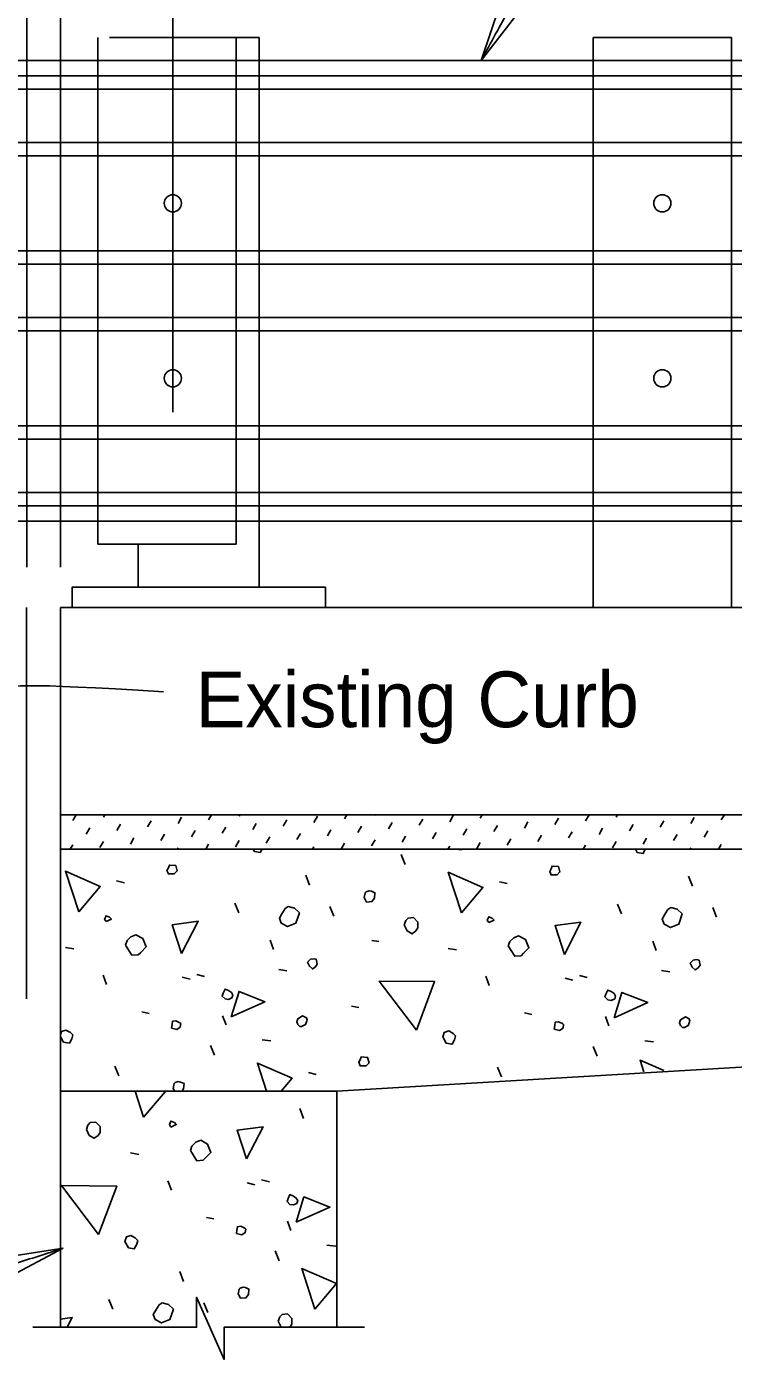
# Model space of a CAD drawing. Extents: x 0 to 41.1, y 0 to 25.9.
# Drawn here: x 27.563 to 30.119, y 5.148 to 9.971 of the extents above; entities that cross this region are included whole.
import ezdxf

# ---------------------------------------------------------------- set-up
doc = ezdxf.new("R2010")
doc.units = 0
for name, color, linetype in [('Dimension', 7, 'Continuous'), ('ExistSuperStruct', 7, 'Continuous'), ('Miscellaneous', 7, 'Continuous'), ('SteelMisc_h', 7, 'Continuous'), ('TextStructures', 7, 'Continuous')]:
    doc.layers.add(name, color=color, linetype=linetype)

msp = doc.modelspace()

# ---------------------------------------------------------------- linework, layer by layer
at = {"layer": 'Dimension'}
for p, q in [((27.5628, 8.0144), (27.5628, 11.1866)), ((27.6853, 8.0144), (27.6853, 11.1866))]:
    msp.add_line(p, q, dxfattribs=at)
for points in [[(29.2068, 9.8481), (29.3364, 10.0149), (29.2743, 10.0483)], [(27.6953, 5.5504), (27.4865, 5.5185), (27.5086, 5.4515)]]:
    msp.add_lwpolyline(points, close=True, dxfattribs=at)
msp.add_lwpolyline([(28.7853, 5.2645), (28.2767, 5.2645), (28.2767, 5.1482), (28.1774, 5.3732), (28.1774, 5.2645), (27.5853, 5.2645)], dxfattribs=at)
for points, degree in [([(30.0832, 10.4986), (29.8429, 10.4986), (29.6309, 10.4986), (29.4118, 10.2299), (29.2069, 9.8481)], 2), ([(28.0581, 7.5636), (27.5366, 7.5973), (27.4332, 7.5751), (27.3392, 7.5386), (27.1681, 7.276)], 3), ([(27.6953, 5.5504), (27.0315, 5.3308), (26.4276, 5.2844)], 2)]:
    msp.add_open_spline(points, degree=degree, dxfattribs=at)
at = {"layer": 'ExistSuperStruct'}
for p, q in [((27.5627, 7.8689), (27.5627, 6.4523)), ((27.6853, 7.869), (27.6853, 5.2644)), ((27.6853, 7.869), (28.6853, 7.869)), ((27.6853, 7.8689), (35.7954, 7.8689)), ((39.26, 7.1191), (27.6853, 7.1191)), ((27.6853, 6.994), (39.26, 6.994)), ((32.9053, 6.369), (28.6853, 6.119)), ((28.6853, 6.119), (27.6853, 6.119)), ((28.6853, 6.119), (28.6853, 5.2644))]:
    msp.add_line(p, q, dxfattribs=at)
at = {"layer": 'Miscellaneous'}
for p, q in [((28.0916, 8.5752), (28.0916, 11.3864)), ((27.8208, 9.9315), (27.8208, 8.0981)), ((27.8626, 9.9315), (28.4041, 9.9315)), ((28.3208, 9.9315), (28.3208, 8.0981)), ((29.6124, 9.9315), (29.6124, 7.869)), ((29.6124, 9.9315), (30.1124, 9.9315)), ((30.1124, 9.9315), (30.1124, 7.869)), ((26.2319, 9.7925), (37.5468, 9.7925)), ((26.2319, 9.7443), (37.5468, 9.7443)), ((26.2319, 9.5515), (37.5468, 9.5515)), ((26.2319, 9.5032), (37.5468, 9.5032)), ((26.2319, 9.1593), (37.5468, 9.1593)), ((26.2319, 9.1111), (37.5468, 9.1111)), ((26.2319, 8.9182), (37.5468, 8.9182)), ((26.2319, 8.8701), (37.5468, 8.8701)), ((26.2319, 8.5262), (37.5468, 8.5262)), ((26.2319, 8.4779), (37.5468, 8.4779)), ((26.2319, 8.2851), (37.5468, 8.2851)), ((26.2319, 8.2369), (37.5468, 8.2369)), ((27.7297, 7.0977), (27.7421, 7.1191)), ((27.8403, 7.1107), (27.8452, 7.1191)), ((27.9998, 7.0748), (28.0128, 7.0972)), ((28.1104, 7.0878), (28.1234, 7.1102)), ((28.2211, 7.1007), (28.2317, 7.1191)), ((28.3317, 7.1137), (28.3348, 7.1191)), ((28.4912, 7.0778), (28.5041, 7.1002)), ((28.6018, 7.0908), (28.6148, 7.1132)), ((28.7124, 7.1038), (28.7213, 7.1191)), ((28.8231, 7.1167), (28.8244, 7.1191)), ((28.8719, 7.0679), (28.8849, 7.0903)), ((28.9825, 7.0809), (28.9955, 7.1032)), ((29.0932, 7.0938), (29.1061, 7.1162)), ((29.2038, 7.1068), (29.2109, 7.1191)), ((29.3633, 7.0709), (29.3762, 7.0933)), ((29.4739, 7.0839), (29.4869, 7.1063)), ((29.5845, 7.0968), (29.5974, 7.1191)), ((29.6952, 7.1098), (29.7005, 7.1191)), ((29.8546, 7.0739), (29.8676, 7.0963)), ((29.9653, 7.0869), (29.9782, 7.1093)), ((30.0759, 7.0999), (30.087, 7.1191)), ((27.7785, 7.0489), (27.7915, 7.0713)), ((27.8892, 7.0619), (27.9021, 7.0842)), ((28.0486, 7.026), (28.0616, 7.0484)), ((28.1593, 7.0389), (28.1722, 7.0613)), ((28.2699, 7.0519), (28.2829, 7.0743)), ((28.3805, 7.0649), (28.3935, 7.0873)), ((28.54, 7.029), (28.553, 7.0514)), ((28.6506, 7.042), (28.6636, 7.0644)), ((28.7613, 7.0549), (28.7742, 7.0773)), ((28.9207, 7.0191), (28.9337, 7.0415)), ((29.0314, 7.032), (29.0443, 7.0544)), ((29.142, 7.045), (29.155, 7.0674)), ((29.2526, 7.058), (29.2656, 7.0803)), ((29.4121, 7.0221), (29.4251, 7.0445)), ((29.5227, 7.035), (29.5357, 7.0574)), ((29.6334, 7.048), (29.6463, 7.0704)), ((29.744, 7.061), (29.757, 7.0834)), ((29.9035, 7.0251), (29.9164, 7.0475)), ((30.0141, 7.0381), (30.0271, 7.0605)), ((27.7207, 6.994), (27.7297, 7.0095)), ((27.8274, 7.0001), (27.8403, 7.0224)), ((27.938, 7.013), (27.951, 7.0354)), ((28.1072, 6.994), (28.1104, 6.9995)), ((28.2104, 6.994), (28.2211, 7.0125)), ((28.3187, 7.0031), (28.3317, 7.0255)), ((28.4294, 7.016), (28.4423, 7.0384)), ((28.5969, 6.994), (28.6018, 7.0026)), ((28.7, 6.994), (28.7124, 7.0155)), ((28.8101, 7.0061), (28.8231, 7.0285)), ((29.0865, 6.994), (29.0932, 7.0056)), ((29.1149, 6.994), (29.1368, 6.9916)), ((29.1908, 6.9962), (29.2038, 7.0185)), ((29.3015, 7.0091), (29.3144, 7.0315)), ((29.473, 6.994), (29.4739, 6.9956)), ((29.5761, 6.994), (29.5845, 7.0086)), ((29.6822, 6.9992), (29.6952, 7.0216)), ((29.7928, 7.0121), (29.8058, 7.0345)), ((29.9626, 6.994), (29.9653, 6.9987)), ((30.0657, 6.994), (30.0759, 7.0116)), ((28.9323, 6.9392), (28.9182, 6.9745)), ((28.5865, 6.8643), (28.5723, 6.8997)), ((29.9711, 6.8608), (29.957, 6.8961)), ((27.8882, 6.8802), (27.9165, 6.8731)), ((29.2729, 6.8767), (29.3012, 6.8696)), ((28.3301, 6.7635), (28.316, 6.7989)), ((28.6742, 6.7518), (28.6601, 6.7871)), ((29.7148, 6.76), (29.7007, 6.7954)), ((30.0589, 6.7483), (30.0448, 6.7836)), ((28.4557, 6.631), (28.4433, 6.6645)), ((28.8121, 6.6634), (28.8369, 6.6599)), ((29.8403, 6.6274), (29.828, 6.661)), ((27.7032, 6.6387), (27.7333, 6.6333)), ((29.0879, 6.6351), (29.1179, 6.6298)), ((28.4745, 6.5591), (28.5045, 6.5538)), ((27.8517, 6.5043), (27.8393, 6.5379)), ((28.1257, 6.5308), (28.154, 6.5237)), ((28.1781, 6.5408), (28.2064, 6.5337)), ((29.2364, 6.5008), (29.224, 6.5344)), ((29.5104, 6.5273), (29.5387, 6.5202)), ((29.5628, 6.5373), (29.5911, 6.5302)), ((29.8592, 6.5556), (29.8892, 6.5503)), ((28.7379, 6.4265), (28.7644, 6.4212)), ((27.979, 6.4053), (28.0055, 6.4)), ((28.2842, 6.3582), (28.2718, 6.3918)), ((29.3637, 6.4018), (29.3902, 6.3965)), ((29.6689, 6.3547), (29.6565, 6.3883)), ((28.2418, 6.2486), (28.2276, 6.284)), ((28.4144, 6.3045), (28.4462, 6.301)), ((29.6264, 6.2451), (29.6123, 6.2804)), ((29.799, 6.301), (29.8309, 6.2975)), ((27.8959, 6.1737), (27.8818, 6.2091)), ((28.5823, 6.1861), (28.6106, 6.179)), ((29.2806, 6.1702), (29.2664, 6.2055)), ((28.5648, 6.0201), (28.5507, 6.0554)), ((27.6853, 5.9202), (27.6869, 5.9199)), ((27.9379, 5.8952), (27.968, 5.8899)), ((28.0864, 5.7608), (28.074, 5.7944)), ((28.3604, 5.7874), (28.3887, 5.7803)), ((28.4128, 5.7973), (28.4411, 5.7903)), ((28.2137, 5.6618), (28.2402, 5.6565)), ((28.5189, 5.6147), (28.5065, 5.6483)), ((28.6491, 5.5611), (28.6809, 5.5575)), ((28.4764, 5.5051), (28.4623, 5.5405)), ((28.1306, 5.4303), (28.1164, 5.4656)), ((27.8743, 5.3295), (27.8601, 5.3649)), ((28.2184, 5.3178), (28.2042, 5.3531))]:
    msp.add_line(p, q, dxfattribs=at)
for points in [[(28.3824, 6.994), (28.3867, 6.9863), (28.4079, 6.9827), (28.4142, 6.994)], [(29.7651, 6.994), (29.7714, 6.9827), (29.7926, 6.9792), (29.8008, 6.994)], [(27.7509, 6.7677), (27.7032, 6.9144), (27.8287, 6.8596), (27.7509, 6.7677)], [(28.0756, 6.905), (28.0968, 6.905), (28.1074, 6.9156), (28.1021, 6.935), (28.0791, 6.9368), (28.0756, 6.9262), (28.0703, 6.9173), (28.0756, 6.905), (28.072, 6.9085)], [(29.1356, 6.7642), (29.0879, 6.9109), (29.2134, 6.8561), (29.1356, 6.7642)], [(29.4603, 6.9014), (29.4815, 6.9014), (29.4921, 6.912), (29.4868, 6.9315), (29.4638, 6.9332), (29.4603, 6.9226), (29.455, 6.9138), (29.4603, 6.9014), (29.4567, 6.905)], [(28.7838, 6.819), (28.7927, 6.8031), (28.8121, 6.8048), (28.821, 6.8172), (28.8227, 6.8366), (28.8103, 6.8419), (28.8015, 6.8437), (28.7909, 6.8402), (28.7874, 6.8366), (28.7838, 6.819)], [(27.8499, 6.7323), (27.8694, 6.7412), (27.8623, 6.7483), (27.8499, 6.7536), (27.8446, 6.7412), (27.8499, 6.7323)], [(28.4839, 6.7264), (28.5069, 6.714), (28.537, 6.7264), (28.5493, 6.7635), (28.5317, 6.7812), (28.5087, 6.7865), (28.4981, 6.7794), (28.4857, 6.76), (28.4769, 6.7441), (28.4839, 6.7264)], [(29.8686, 6.7229), (29.8916, 6.7105), (29.9216, 6.7229), (29.934, 6.76), (29.9163, 6.7777), (29.8934, 6.783), (29.8828, 6.7759), (29.8704, 6.7565), (29.8615, 6.7406), (29.8686, 6.7229)], [(28.1233, 6.6168), (28.0897, 6.7211), (28.1834, 6.7335), (28.1233, 6.6168)], [(28.9288, 6.72), (28.9394, 6.6988), (28.9571, 6.6881), (28.9712, 6.6988), (28.9783, 6.7094), (28.9783, 6.7306), (28.9624, 6.7465), (28.9429, 6.7447), (28.9341, 6.7359), (28.9288, 6.72)], [(29.2346, 6.7288), (29.2541, 6.7376), (29.247, 6.7447), (29.2346, 6.75), (29.2293, 6.7376), (29.2346, 6.7288)], [(29.508, 6.6133), (29.4744, 6.7176), (29.5681, 6.7299), (29.508, 6.6133)], [(27.9206, 6.6475), (27.9436, 6.6104), (27.9666, 6.6121), (27.9754, 6.621), (27.9949, 6.6404), (27.9825, 6.6705), (27.9578, 6.6846), (27.9401, 6.6775), (27.926, 6.6634), (27.9206, 6.6475)], [(29.3053, 6.644), (29.3283, 6.6068), (29.3513, 6.6086), (29.3601, 6.6174), (29.3796, 6.6369), (29.3672, 6.6669), (29.3424, 6.6811), (29.3248, 6.674), (29.3106, 6.6599), (29.3053, 6.644)], [(28.5858, 6.5715), (28.5964, 6.5609), (28.6071, 6.5679), (28.6141, 6.5785), (28.6106, 6.5962), (28.6018, 6.598), (28.5894, 6.5962), (28.5788, 6.5856), (28.5858, 6.5715)], [(29.9705, 6.5679), (29.9811, 6.5573), (29.9917, 6.5644), (29.9988, 6.575), (29.9953, 6.5927), (29.9864, 6.5945), (29.9741, 6.5927), (29.9634, 6.5821), (29.9705, 6.5679)], [(28.973, 6.3399), (28.8386, 6.5167), (29.0384, 6.5149), (28.973, 6.3399)], [(28.2806, 6.4524), (28.293, 6.4506), (28.3054, 6.4559), (28.3089, 6.4666), (28.3036, 6.4754), (28.293, 6.4825), (28.2806, 6.4878), (28.2736, 6.4736), (28.27, 6.463), (28.2806, 6.4524)], [(28.303, 6.3876), (28.3313, 6.4796), (28.425, 6.4424), (28.303, 6.3876)], [(29.6653, 6.4489), (29.6777, 6.4471), (29.6901, 6.4524), (29.6936, 6.463), (29.6883, 6.4719), (29.6777, 6.4789), (29.6653, 6.4842), (29.6583, 6.4701), (29.6547, 6.4595), (29.6653, 6.4489)], [(29.6877, 6.3841), (29.716, 6.476), (29.8097, 6.4389), (29.6877, 6.3841)], [(28.0868, 6.347), (28.1063, 6.3417), (28.1186, 6.3505), (28.1204, 6.3629), (28.1169, 6.3664), (28.1027, 6.3735), (28.0904, 6.3717), (28.0886, 6.3593), (28.0868, 6.347)], [(28.5505, 6.3523), (28.5576, 6.3523), (28.5717, 6.3593), (28.577, 6.3753), (28.5752, 6.3841), (28.5611, 6.3912), (28.5434, 6.3806), (28.5399, 6.3699), (28.5434, 6.3593), (28.5505, 6.3523)], [(29.4715, 6.3434), (29.4909, 6.3381), (29.5033, 6.347), (29.5051, 6.3593), (29.5015, 6.3629), (29.4874, 6.3699), (29.475, 6.3682), (29.4733, 6.3558), (29.4715, 6.3434)], [(29.9352, 6.3487), (29.9422, 6.3487), (29.9564, 6.3558), (29.9617, 6.3717), (29.9599, 6.3806), (29.9458, 6.3876), (29.9281, 6.377), (29.9246, 6.3664), (29.9281, 6.3558), (29.9352, 6.3487)], [(27.6873, 6.3116), (27.6961, 6.2957), (27.7174, 6.2922), (27.7262, 6.3081), (27.7297, 6.3222), (27.7209, 6.3311), (27.705, 6.3399), (27.6891, 6.3346), (27.6853, 6.3233)], [(29.072, 6.3081), (29.0808, 6.2922), (29.102, 6.2886), (29.1109, 6.3045), (29.1144, 6.3187), (29.1056, 6.3275), (29.0897, 6.3364), (29.0737, 6.3311), (29.0684, 6.3151), (29.072, 6.3081)], [(27.6853, 6.3156), (27.6873, 6.3116)], [(28.7697, 6.2109), (28.7909, 6.2109), (28.8015, 6.2215), (28.7962, 6.2409), (28.7732, 6.2427), (28.7697, 6.2321), (28.7644, 6.2232), (28.7697, 6.2109), (28.7662, 6.2144)], [(29.7957, 6.1887), (29.782, 6.2308), (29.8682, 6.1932)], [(28.4303, 6.119), (28.3973, 6.2203), (28.5228, 6.1655), (28.4834, 6.119)], [(28.1249, 6.119), (28.1304, 6.1266), (28.1322, 6.1461), (28.1198, 6.1514), (28.1109, 6.1531), (28.1003, 6.1496), (28.0968, 6.1461), (28.0933, 6.1284)], [(28.0933, 6.1284), (28.0985, 6.119)], [(27.9856, 6.0242), (27.9548, 6.119)], [(28.057, 6.119), (28.0634, 6.1162), (27.9856, 6.0242)], [(27.7788, 5.98), (27.7894, 5.9588), (27.8071, 5.9482), (27.8212, 5.9588), (27.8283, 5.9694), (27.8283, 5.9906), (27.8124, 6.0066), (27.7929, 6.0048), (27.7841, 5.9959), (27.7788, 5.98)], [(28.0846, 5.9889), (28.1041, 5.9977), (28.097, 6.0048), (28.0846, 6.0101), (28.0793, 5.9977), (28.0846, 5.9889)], [(28.358, 5.8733), (28.3244, 5.9776), (28.4181, 5.99), (28.358, 5.8733)], [(28.1553, 5.904), (28.1783, 5.8669), (28.2013, 5.8687), (28.2101, 5.8775), (28.2296, 5.897), (28.2172, 5.927), (28.1925, 5.9411), (28.1748, 5.9341), (28.1606, 5.9199), (28.1553, 5.904)], [(27.823, 5.6), (27.6886, 5.7767), (27.8884, 5.775), (27.823, 5.6)], [(28.5153, 5.7089), (28.5277, 5.7072), (28.5401, 5.7125), (28.5436, 5.7231), (28.5383, 5.7319), (28.5277, 5.739), (28.5153, 5.7443), (28.5083, 5.7302), (28.5047, 5.7196), (28.5153, 5.7089)], [(28.5377, 5.6442), (28.566, 5.7361), (28.6597, 5.699), (28.5377, 5.6442)], [(27.922, 5.5681), (27.9308, 5.5522), (27.952, 5.5487), (27.9609, 5.5646), (27.9644, 5.5788), (27.9556, 5.5876), (27.9397, 5.5964), (27.9238, 5.5911), (27.9185, 5.5752), (27.922, 5.5681)], [(28.3215, 5.6035), (28.341, 5.5982), (28.3533, 5.607), (28.3551, 5.6194), (28.3516, 5.623), (28.3374, 5.63), (28.325, 5.6283), (28.3233, 5.6159), (28.3215, 5.6035)], [(28.6058, 5.3301), (28.5581, 5.4769), (28.6836, 5.4221), (28.6058, 5.3301)], [(28.328, 5.3849), (28.3368, 5.369), (28.3562, 5.3708), (28.3651, 5.3832), (28.3668, 5.4026), (28.3545, 5.4079), (28.3456, 5.4097), (28.335, 5.4061), (28.3315, 5.4026), (28.328, 5.3849)], [(28.0281, 5.2924), (28.051, 5.28), (28.0811, 5.2924), (28.0935, 5.3295), (28.0758, 5.3472), (28.0528, 5.3525), (28.0422, 5.3454), (28.0298, 5.326), (28.021, 5.3101), (28.0281, 5.2924)], [(28.5149, 5.2644), (28.5153, 5.2647), (28.5224, 5.2753), (28.5224, 5.2965), (28.5065, 5.3124), (28.4871, 5.3107), (28.4782, 5.3018), (28.4729, 5.2859)], [(27.6853, 5.2939), (27.7275, 5.2994), (27.7094, 5.2643)], [(28.4729, 5.2859), (28.4835, 5.2647), (28.4841, 5.2644)]]:
    msp.add_lwpolyline(points, dxfattribs=at)
for centre in [(28.0916, 9.3314), (28.0916, 8.6982)]:
    msp.add_circle(centre, 0.0312, dxfattribs=at)
at = {"layer": 'SteelMisc_h'}
for p, q in [((28.4041, 9.9315), (28.4041, 7.9419)), ((37.5468, 9.848), (26.2319, 9.848)), ((37.5468, 8.1814), (26.2319, 8.1814)), ((28.3208, 8.0981), (27.8208, 8.0981)), ((27.9666, 8.0981), (27.9666, 7.9419))]:
    msp.add_line(p, q, dxfattribs=at)
msp.add_lwpolyline([(27.727, 7.869), (27.727, 7.9419), (28.6436, 7.9419), (28.6436, 7.869)], close=True, dxfattribs=at)
for centre in [(29.8624, 9.3314), (29.8624, 8.6982)]:
    msp.add_circle(centre, 0.0312, dxfattribs=at)

# ---------------------------------------------------------------- texts
at = {"layer": 'TextStructures'}
msp.add_text('Existing Curb', height=0.2016, dxfattribs=at).set_placement((28.1743, 7.4356))

doc.saveas('drawing.dxf')
